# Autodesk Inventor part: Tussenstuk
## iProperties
Created: 2007-06
Part Number: Tussenstuk
Material: Steel
Document SubType Name: Modeling
Designer: Phil Trethewie
Author: Phil Trethewie
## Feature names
1. Extrusion1
